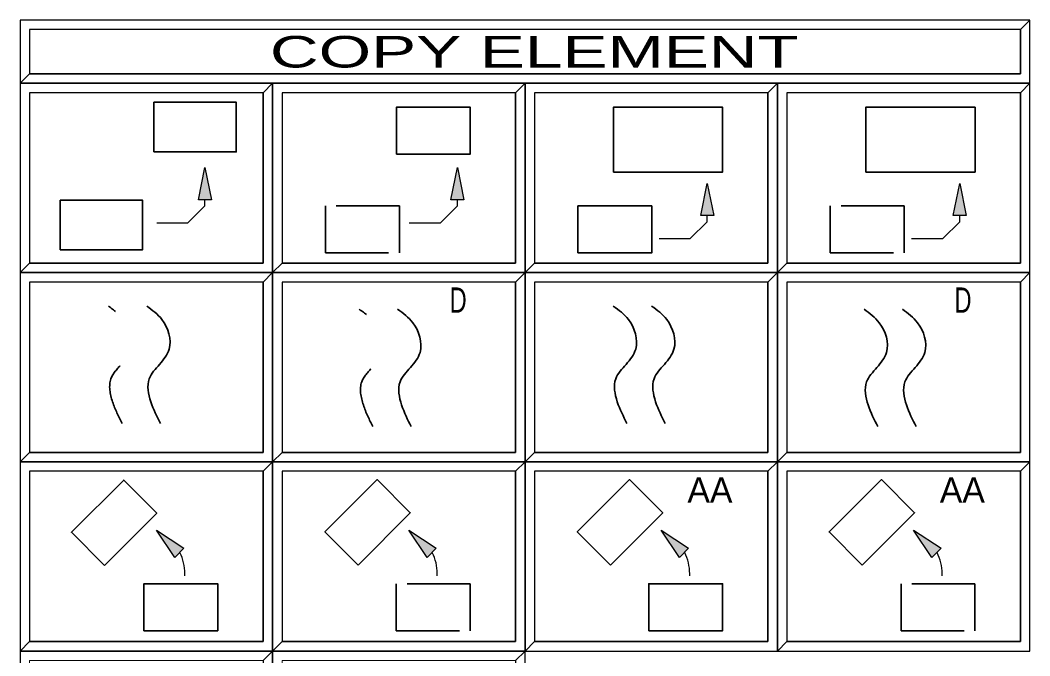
# Model space of a CAD drawing. Extents: x 95906.8 to 95923.6, y 90964.8 to 90972.8.
# Drawn here: x 95912.632 to 95914.232, y 90967.254 to 90968.262 of the extents above; entities that cross this region are included whole.
import ezdxf
from ezdxf.enums import TextEntityAlignment as Align

# ---------------------------------------------------------------- set-up
doc = ezdxf.new("R2010")
doc.units = 0
doc.header["$LTSCALE"] = 0.019
doc.linetypes.add('MEDIUM_DASHED', pattern=[4.5, 3, -1.5])
for name, color, linetype, lineweight in [('1', 7, 'Continuous', 25), ('11', 7, 'Continuous', 25), ('18', 7, 'Continuous', 25), ('2', 7, 'Continuous', 13), ('3', 7, 'Continuous', 25), ('6', 7, 'Continuous', 35), ('7', 7, 'Continuous', 35)]:
    doc.layers.add(name, color=color, linetype=linetype, lineweight=lineweight)

msp = doc.modelspace()

# ---------------------------------------------------------------- hatches: boundary and pattern name
at = {"layer": '6'}
for points in [[(95912.9149, 90967.9769), (95912.9251, 90968.0281), (95912.9353, 90967.9769)], [(95913.3149, 90967.9769), (95913.3251, 90968.0281), (95913.3353, 90967.9769)], [(95913.711, 90967.9519), (95913.7212, 90968.0031), (95913.7314, 90967.9519)], [(95914.111, 90967.9519), (95914.1212, 90968.0031), (95914.1314, 90967.9519)], [(95912.8772, 90967.4102), (95912.8482, 90967.4536), (95912.8916, 90967.4246)], [(95913.2772, 90967.4102), (95913.2482, 90967.4536), (95913.2916, 90967.4246)], [(95913.6772, 90967.4102), (95913.6482, 90967.4536), (95913.6916, 90967.4246)], [(95914.0772, 90967.4102), (95914.0482, 90967.4536), (95914.0916, 90967.4246)]]:
    msp.add_hatch(color=256, dxfattribs=at).paths.add_polyline_path(points)

# ---------------------------------------------------------------- linework, layer by layer
at = {"layer": '1'}
for points in [[(95912.6323, 90968.1617), (95914.2323, 90968.1617), (95914.2323, 90968.2617), (95912.6323, 90968.2617)], [(95912.6323, 90967.8617), (95913.0323, 90967.8617), (95913.0323, 90968.1617), (95912.6323, 90968.1617)], [(95913.0323, 90967.8617), (95913.4323, 90967.8617), (95913.4323, 90968.1617), (95913.0323, 90968.1617)], [(95913.4323, 90967.8617), (95913.8323, 90967.8617), (95913.8323, 90968.1617), (95913.4323, 90968.1617)], [(95913.8323, 90967.8617), (95914.2323, 90967.8617), (95914.2323, 90968.1617), (95913.8323, 90968.1617)], [(95912.6323, 90967.5617), (95913.0323, 90967.5617), (95913.0323, 90967.8617), (95912.6323, 90967.8617)], [(95913.0323, 90967.5617), (95913.4323, 90967.5617), (95913.4323, 90967.8617), (95913.0323, 90967.8617)], [(95913.4323, 90967.5617), (95913.8323, 90967.5617), (95913.8323, 90967.8617), (95913.4323, 90967.8617)], [(95913.8323, 90967.5617), (95914.2323, 90967.5617), (95914.2323, 90967.8617), (95913.8323, 90967.8617)], [(95912.6323, 90967.2617), (95913.0323, 90967.2617), (95913.0323, 90967.5617), (95912.6323, 90967.5617)], [(95913.0323, 90967.2617), (95913.4323, 90967.2617), (95913.4323, 90967.5617), (95913.0323, 90967.5617)], [(95913.4323, 90967.2617), (95913.8323, 90967.2617), (95913.8323, 90967.5617), (95913.4323, 90967.5617)], [(95913.8323, 90967.2617), (95914.2323, 90967.2617), (95914.2323, 90967.5617), (95913.8323, 90967.5617)], [(95912.6323, 90966.9617), (95913.0323, 90966.9617), (95913.0323, 90967.2617), (95912.6323, 90967.2617)], [(95913.0323, 90966.9617), (95913.4323, 90966.9617), (95913.4323, 90967.2617), (95913.0323, 90967.2617)]]:
    msp.add_lwpolyline(points, close=True, dxfattribs=at)
at = {"layer": '11'}
for points in [[(95912.6473, 90967.8767), (95913.0173, 90967.8767), (95913.0173, 90968.1467), (95912.6473, 90968.1467)], [(95913.0473, 90967.8767), (95913.4173, 90967.8767), (95913.4173, 90968.1467), (95913.0473, 90968.1467)], [(95913.4473, 90967.8767), (95913.8173, 90967.8767), (95913.8173, 90968.1467), (95913.4473, 90968.1467)], [(95913.8473, 90967.8767), (95914.2173, 90967.8767), (95914.2173, 90968.1467), (95913.8473, 90968.1467)], [(95912.6473, 90967.5767), (95913.0173, 90967.5767), (95913.0173, 90967.8467), (95912.6473, 90967.8467)], [(95913.0473, 90967.5767), (95913.4173, 90967.5767), (95913.4173, 90967.8467), (95913.0473, 90967.8467)], [(95913.4473, 90967.5767), (95913.8173, 90967.5767), (95913.8173, 90967.8467), (95913.4473, 90967.8467)], [(95913.8473, 90967.5767), (95914.2173, 90967.5767), (95914.2173, 90967.8467), (95913.8473, 90967.8467)], [(95912.6473, 90967.2767), (95913.0173, 90967.2767), (95913.0173, 90967.5467), (95912.6473, 90967.5467)], [(95913.0473, 90967.2767), (95913.4173, 90967.2767), (95913.4173, 90967.5467), (95913.0473, 90967.5467)], [(95913.4473, 90967.2767), (95913.8173, 90967.2767), (95913.8173, 90967.5467), (95913.4473, 90967.5467)], [(95913.8473, 90967.2767), (95914.2173, 90967.2767), (95914.2173, 90967.5467), (95913.8473, 90967.5467)]]:
    msp.add_lwpolyline(points, close=True, dxfattribs=at)
at = {"layer": '18'}
msp.add_lwpolyline([(95912.6473, 90968.1767), (95914.2173, 90968.1767), (95914.2173, 90968.2467), (95912.6473, 90968.2467)], close=True, dxfattribs=at)
at = {"layer": '2'}
for points in [[(95912.6323, 90968.2617), (95912.6323, 90968.1617), (95912.6473, 90968.1767), (95912.6473, 90968.2467), (95914.2173, 90968.2467), (95914.2323, 90968.2617)], [(95912.6323, 90968.1617), (95912.6323, 90967.8617), (95912.6473, 90967.8767), (95912.6473, 90968.1467), (95913.0173, 90968.1467), (95913.0323, 90968.1617)], [(95913.0323, 90968.1617), (95913.0323, 90967.8617), (95913.0473, 90967.8767), (95913.0473, 90968.1467), (95913.4173, 90968.1467), (95913.4323, 90968.1617)], [(95913.4323, 90968.1617), (95913.4323, 90967.8617), (95913.4473, 90967.8767), (95913.4473, 90968.1467), (95913.8173, 90968.1467), (95913.8323, 90968.1617)], [(95913.8323, 90968.1617), (95913.8323, 90967.8617), (95913.8473, 90967.8767), (95913.8473, 90968.1467), (95914.2173, 90968.1467), (95914.2323, 90968.1617)], [(95912.6323, 90967.8617), (95912.6323, 90967.5617), (95912.6473, 90967.5767), (95912.6473, 90967.8467), (95913.0173, 90967.8467), (95913.0323, 90967.8617)], [(95913.0323, 90967.8617), (95913.0323, 90967.5617), (95913.0473, 90967.5767), (95913.0473, 90967.8467), (95913.4173, 90967.8467), (95913.4323, 90967.8617)], [(95913.4323, 90967.8617), (95913.4323, 90967.5617), (95913.4473, 90967.5767), (95913.4473, 90967.8467), (95913.8173, 90967.8467), (95913.8323, 90967.8617)], [(95913.8323, 90967.8617), (95913.8323, 90967.5617), (95913.8473, 90967.5767), (95913.8473, 90967.8467), (95914.2173, 90967.8467), (95914.2323, 90967.8617)], [(95912.6323, 90967.5617), (95912.6323, 90967.2617), (95912.6473, 90967.2767), (95912.6473, 90967.5467), (95913.0173, 90967.5467), (95913.0323, 90967.5617)], [(95913.0323, 90967.5617), (95913.0323, 90967.2617), (95913.0473, 90967.2767), (95913.0473, 90967.5467), (95913.4173, 90967.5467), (95913.4323, 90967.5617)], [(95913.4323, 90967.5617), (95913.4323, 90967.2617), (95913.4473, 90967.2767), (95913.4473, 90967.5467), (95913.8173, 90967.5467), (95913.8323, 90967.5617)], [(95913.8323, 90967.5617), (95913.8323, 90967.2617), (95913.8473, 90967.2767), (95913.8473, 90967.5467), (95914.2173, 90967.5467), (95914.2323, 90967.5617)], [(95912.6323, 90967.2617), (95912.6323, 90966.9617), (95912.6473, 90966.9767), (95912.6473, 90967.2467), (95913.0173, 90967.2467), (95913.0323, 90967.2617)], [(95913.0323, 90967.2617), (95913.0323, 90966.9617), (95913.0473, 90966.9767), (95913.0473, 90967.2467), (95913.4173, 90967.2467), (95913.4323, 90967.2617)]]:
    msp.add_lwpolyline(points, close=True, dxfattribs=at)
at = {"layer": '3'}
for points in [[(95912.6323, 90968.1617), (95914.2323, 90968.1617), (95914.2323, 90968.2617), (95914.2173, 90968.2467), (95914.2173, 90968.1767), (95912.6473, 90968.1767)], [(95912.6323, 90967.8617), (95913.0323, 90967.8617), (95913.0323, 90968.1617), (95913.0173, 90968.1467), (95913.0173, 90967.8767), (95912.6473, 90967.8767)], [(95913.0323, 90967.8617), (95913.4323, 90967.8617), (95913.4323, 90968.1617), (95913.4173, 90968.1467), (95913.4173, 90967.8767), (95913.0473, 90967.8767)], [(95913.4323, 90967.8617), (95913.8323, 90967.8617), (95913.8323, 90968.1617), (95913.8173, 90968.1467), (95913.8173, 90967.8767), (95913.4473, 90967.8767)], [(95913.8323, 90967.8617), (95914.2323, 90967.8617), (95914.2323, 90968.1617), (95914.2173, 90968.1467), (95914.2173, 90967.8767), (95913.8473, 90967.8767)], [(95912.6323, 90967.5617), (95913.0323, 90967.5617), (95913.0323, 90967.8617), (95913.0173, 90967.8467), (95913.0173, 90967.5767), (95912.6473, 90967.5767)], [(95913.0323, 90967.5617), (95913.4323, 90967.5617), (95913.4323, 90967.8617), (95913.4173, 90967.8467), (95913.4173, 90967.5767), (95913.0473, 90967.5767)], [(95913.4323, 90967.5617), (95913.8323, 90967.5617), (95913.8323, 90967.8617), (95913.8173, 90967.8467), (95913.8173, 90967.5767), (95913.4473, 90967.5767)], [(95913.8323, 90967.5617), (95914.2323, 90967.5617), (95914.2323, 90967.8617), (95914.2173, 90967.8467), (95914.2173, 90967.5767), (95913.8473, 90967.5767)], [(95912.6323, 90967.2617), (95913.0323, 90967.2617), (95913.0323, 90967.5617), (95913.0173, 90967.5467), (95913.0173, 90967.2767), (95912.6473, 90967.2767)], [(95913.0323, 90967.2617), (95913.4323, 90967.2617), (95913.4323, 90967.5617), (95913.4173, 90967.5467), (95913.4173, 90967.2767), (95913.0473, 90967.2767)], [(95913.4323, 90967.2617), (95913.8323, 90967.2617), (95913.8323, 90967.5617), (95913.8173, 90967.5467), (95913.8173, 90967.2767), (95913.4473, 90967.2767)], [(95913.8323, 90967.2617), (95914.2323, 90967.2617), (95914.2323, 90967.5617), (95914.2173, 90967.5467), (95914.2173, 90967.2767), (95913.8473, 90967.2767)], [(95912.6323, 90966.9617), (95913.0323, 90966.9617), (95913.0323, 90967.2617), (95913.0173, 90967.2467), (95913.0173, 90966.9767), (95912.6473, 90966.9767)], [(95913.0323, 90966.9617), (95913.4323, 90966.9617), (95913.4323, 90967.2617), (95913.4173, 90967.2467), (95913.4173, 90966.9767), (95913.0473, 90966.9767)]]:
    msp.add_lwpolyline(points, close=True, dxfattribs=at)
at = {"layer": '6', "lineweight": 25}
for p, q in [((95912.8933, 90967.381), (95912.8933, 90967.3844)), ((95913.2933, 90967.381), (95913.2933, 90967.3844)), ((95913.6933, 90967.381), (95913.6933, 90967.3844)), ((95914.0933, 90967.381), (95914.0933, 90967.3844))]:
    msp.add_line(p, q, dxfattribs=at)
at = {"layer": '6'}
for points in [[(95912.8442, 90968.0528), (95912.9747, 90968.0528), (95912.9747, 90968.1315), (95912.8442, 90968.1315)], [(95913.2284, 90968.0495), (95913.3455, 90968.0495), (95913.3455, 90968.1238), (95913.2284, 90968.1238)], [(95913.5724, 90968.021), (95913.7455, 90968.021), (95913.7455, 90968.1238), (95913.5724, 90968.1238)], [(95913.9724, 90968.021), (95914.1455, 90968.021), (95914.1455, 90968.1238), (95913.9724, 90968.1238)], [(95912.6957, 90967.8977), (95912.8262, 90967.8977), (95912.8262, 90967.9764), (95912.6957, 90967.9764)], [(95913.5161, 90967.8929), (95913.6332, 90967.8929), (95913.6332, 90967.9672), (95913.5161, 90967.9672)], [(95912.766, 90967.3975), (95912.8488, 90967.4803), (95912.7963, 90967.5328), (95912.7135, 90967.45)], [(95913.1677, 90967.3981), (95913.2505, 90967.4809), (95913.198, 90967.5334), (95913.1152, 90967.4506)], [(95913.5677, 90967.3981), (95913.6505, 90967.4809), (95913.598, 90967.5334), (95913.5152, 90967.4506)], [(95913.9668, 90967.3981), (95914.0496, 90967.4809), (95913.9971, 90967.5334), (95913.9143, 90967.4506)], [(95912.8283, 90967.294), (95912.9454, 90967.294), (95912.9454, 90967.3683), (95912.8283, 90967.3683)], [(95913.6283, 90967.294), (95913.7454, 90967.294), (95913.7454, 90967.3683), (95913.6283, 90967.3683)]]:
    msp.add_lwpolyline(points, close=True, dxfattribs=at)
at = {"layer": '6', "lineweight": 25}
for points in [[(95912.9149, 90967.9769), (95912.9251, 90968.0281), (95912.9353, 90967.9769)], [(95913.3149, 90967.9769), (95913.3251, 90968.0281), (95913.3353, 90967.9769)], [(95913.711, 90967.9519), (95913.7212, 90968.0031), (95913.7314, 90967.9519)], [(95914.111, 90967.9519), (95914.1212, 90968.0031), (95914.1314, 90967.9519)], [(95912.8772, 90967.4102), (95912.8482, 90967.4536), (95912.8916, 90967.4246)], [(95913.2772, 90967.4102), (95913.2482, 90967.4536), (95913.2916, 90967.4246)], [(95913.6772, 90967.4102), (95913.6482, 90967.4536), (95913.6916, 90967.4246)], [(95914.0772, 90967.4102), (95914.0482, 90967.4536), (95914.0916, 90967.4246)]]:
    msp.add_lwpolyline(points, close=True, dxfattribs=at)
for points in [[(95912.8487, 90967.9404), (95912.8982, 90967.9404), (95912.9251, 90967.9673), (95912.9251, 90967.9769)], [(95913.2487, 90967.9404), (95913.2982, 90967.9404), (95913.3251, 90967.9673), (95913.3251, 90967.9769)], [(95913.6448, 90967.9154), (95913.6943, 90967.9154), (95913.7212, 90967.9423), (95913.7212, 90967.9519)], [(95914.0448, 90967.9154), (95914.0943, 90967.9154), (95914.1212, 90967.9423), (95914.1212, 90967.9519)]]:
    msp.add_lwpolyline(points, dxfattribs=at)
at = {"layer": '6', "linetype": 'MEDIUM_DASHED'}
for points in [[(95913.1161, 90967.8929), (95913.2332, 90967.8929), (95913.2332, 90967.9672), (95913.1161, 90967.9672)], [(95913.9161, 90967.8929), (95914.0332, 90967.8929), (95914.0332, 90967.9672), (95913.9161, 90967.9672)], [(95913.2283, 90967.294), (95913.3454, 90967.294), (95913.3454, 90967.3683), (95913.2283, 90967.3683)], [(95914.0283, 90967.294), (95914.1454, 90967.294), (95914.1454, 90967.3683), (95914.0283, 90967.3683)]]:
    msp.add_lwpolyline(points, close=True, dxfattribs=at)
at = {"layer": '6', "lineweight": 25}
for centre in [(95912.8183, 90967.3844), (95913.2183, 90967.3844), (95913.6183, 90967.3844), (95914.0183, 90967.3844)]:
    msp.add_arc(centre, 0.075, 0, 26.5009, dxfattribs=at)
at = {"layer": '6', "linetype": 'MEDIUM_DASHED'}
for points in [[(95912.7938, 90967.6226), (95912.7786, 90967.6568), (95912.7761, 90967.6934), (95912.7925, 90967.7162), (95912.8077, 90967.7402), (95912.7963, 90967.7871), (95912.7722, 90967.8085)], [(95913.1913, 90967.6176), (95913.1761, 90967.6518), (95913.1736, 90967.6884), (95913.19, 90967.7112), (95913.2052, 90967.7352), (95913.1938, 90967.7821), (95913.1697, 90967.8035)]]:
    msp.add_spline(points, degree=3, dxfattribs=at)
at = {"layer": '6'}
for points in [[(95912.8545, 90967.6226), (95912.8393, 90967.6568), (95912.8368, 90967.6934), (95912.8532, 90967.7162), (95912.8684, 90967.7402), (95912.857, 90967.7871), (95912.833, 90967.8085)], [(95913.5938, 90967.6226), (95913.5786, 90967.6568), (95913.5761, 90967.6934), (95913.5925, 90967.7162), (95913.6077, 90967.7402), (95913.5963, 90967.7871), (95913.5722, 90967.8085)], [(95913.6545, 90967.6226), (95913.6393, 90967.6568), (95913.6368, 90967.6934), (95913.6532, 90967.7162), (95913.6684, 90967.7402), (95913.657, 90967.7871), (95913.633, 90967.8085)], [(95913.252, 90967.6176), (95913.2368, 90967.6518), (95913.2343, 90967.6884), (95913.2507, 90967.7112), (95913.2659, 90967.7352), (95913.2545, 90967.7821), (95913.2305, 90967.8035)], [(95913.9913, 90967.6176), (95913.9761, 90967.6518), (95913.9736, 90967.6884), (95913.99, 90967.7112), (95914.0052, 90967.7352), (95913.9938, 90967.7821), (95913.9697, 90967.8035)], [(95914.052, 90967.6176), (95914.0368, 90967.6518), (95914.0343, 90967.6884), (95914.0507, 90967.7112), (95914.0659, 90967.7352), (95914.0545, 90967.7821), (95914.0305, 90967.8035)]]:
    msp.add_spline(points, degree=3, dxfattribs=at)

# ---------------------------------------------------------------- texts
at = {"layer": '6', "width": 0.7}
for p in [(95913.3264, 90967.7981), (95914.1264, 90967.7981)]:
    msp.add_text('D', height=0.04, dxfattribs=at).set_placement(p, align=Align.CENTER)
at = {"layer": '6'}
for p in [(95913.7254, 90967.497), (95914.1254, 90967.497)]:
    msp.add_text('AA', height=0.04, dxfattribs=at).set_placement(p, align=Align.CENTER)
at = {"layer": '7', "width": 1.6}
msp.add_text('      COPY ELEMENT     ', height=0.04999, dxfattribs=at).set_placement((95913.4322, 90968.1867), align=Align.CENTER)

doc.saveas('drawing.dxf')
